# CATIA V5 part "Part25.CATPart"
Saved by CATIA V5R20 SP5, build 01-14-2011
Part number: Part25
Material "Water": density 1000 kg/m3
Bounding box of the stored display mesh (mm): x -1.919 to 1.919, y -2 to 2, z -1.919 to 1.919
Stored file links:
  D:\新建文件夹\Part25.CATPart
  C:\Program Files\Dassault Systemes\B20\intel_a\startup\materials\Catalog.CATMaterial
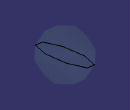
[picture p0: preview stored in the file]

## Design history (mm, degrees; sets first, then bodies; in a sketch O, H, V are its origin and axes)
Body1 (main body), material "Water"
  Sketch1 on xy-plane, origin (0, 0, 0), H (1, 0, 0), V (0, 1, 0)
    arc A1 centre (0, 0) radius 2 from (0, -2) to (0, 2) ccw
    axis line L1 (0, 2.6954) -> (0, -2.923)
    point P1 (0, 2.6954)
    point P3 (0, 2)
    point P4 (0, -2)
    radius A1 = 2
    coincidence: P1 V, L1 P3, L1 P4
    vertical: L1 V
  Shaft1: profile Sketch1, axis Sketch1.L1, angle 360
